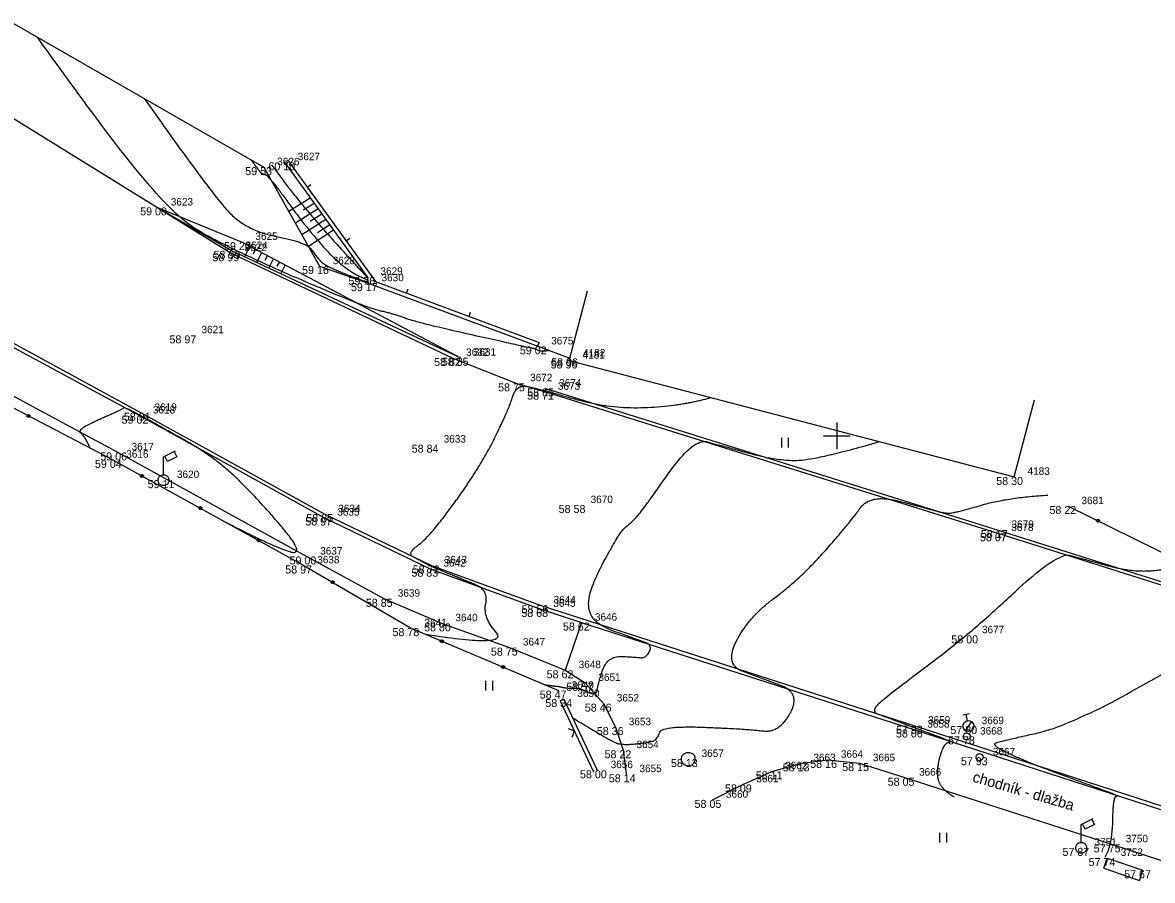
# Model space of a CAD drawing. Extents: x -704017 to -701500, y -1008977 to -1008450.
# Drawn here: x -701980.53 to -701938.17, y -1008866.67 to -1008834.5 of the extents above; entities that cross this region are included whole.
import ezdxf

# ---------------------------------------------------------------- set-up
doc = ezdxf.new("R2010")
doc.units = 0
for name, color, linetype in [('Z_body', 7, 'Continuous'), ('Z_body_cisla', 7, 'Continuous'), ('Z_body_vysky', 7, 'Continuous'), ('Z_budovy', 7, 'Continuous'), ('Z_chodnik', 7, 'Continuous'), ('Z_hekt_sit', 7, 'Continuous'), ('Z_komunikace', 7, 'Continuous'), ('Z_obruby', 7, 'Continuous'), ('Z_oploceni', 7, 'Continuous'), ('Z_popis', 7, 'Continuous'), ('Z_rozhrani_ploch', 7, 'Continuous'), ('Z_site_znaky_kanalizace', 7, 'Continuous'), ('Z_site_znaky_pilire', 7, 'Continuous'), ('Z_site_znaky_VO', 7, 'Continuous'), ('Z_site_znaky_vodovod', 7, 'Continuous'), ('Z_teren_hrany_paty', 7, 'Continuous'), ('Z_vrstevnice_hlavni', 7, 'Continuous'), ('Z_vrstevnice_vedlejsi', 7, 'Continuous'), ('Z_vstupy', 7, 'Continuous'), ('Z_zabradli', 7, 'Continuous')]:
    doc.layers.add(name, color=color, linetype=linetype)

# ---------------------------------------------------------------- blocks, each defined once
blk = doc.blocks.new('POINT_DISPLAY')
blk.add_line((0, 0), (0, 0))
blk = doc.blocks.new('Z210')
blk.add_line((0, 0), (0, 0.17))
blk = doc.blocks.new('Z530')
for p, q in [((-0.05, 0.03), (-0.03, 0.05)), ((-0.05, -0.03), (-0.05, 0.03)), ((-0.03, 0.05), (0.03, 0.05)), ((-0.03, -0.03), (-0.03, 0.03)), ((-0.03, 0.03), (0.03, 0.03)), ((-0.03, -0.03), (0.03, 0.03)), ((0.03, 0.05), (0.05, 0.03)), ((0.03, 0.03), (0.03, -0.03)), ((0.05, 0.03), (0.05, -0.03)), ((-0.03, -0.05), (-0.05, -0.03)), ((0.03, -0.03), (-0.03, -0.03)), ((0.03, -0.05), (-0.03, -0.05)), ((0.05, -0.03), (0.03, -0.05))]:
    blk.add_line(p, q)
blk = doc.blocks.new('Z212')
for p, q in [((-0.17, 0.17), (0, 0)), ((0, 0), (0.17, 0.17))]:
    blk.add_line(p, q)
blk = doc.blocks.new('Z306')
for p, q in [((-0.13, 0.17), (-0.13, -0.2)), ((0.13, 0.17), (0.13, -0.2))]:
    blk.add_line(p, q)
blk = doc.blocks.new('Z13')
for p, q in [((0, 0.88), (0.45, 1.1)), ((0, 0.2), (0, 0.88)), ((0.15, 0.7), (0.05, 0.9)), ((0.5, 0.88), (0.15, 0.7)), ((0.4, 1.07), (0.5, 0.88)), ((-0.2, 0.05), (-0.15, 0.15)), ((-0.2, -0.05), (-0.2, 0.05)), ((-0.15, 0.15), (-0.05, 0.2)), ((-0.05, 0.2), (0.05, 0.2)), ((0.05, 0.2), (0.15, 0.15)), ((0.15, 0.15), (0.2, 0.05)), ((0.2, 0.05), (0.2, -0.05)), ((-0.15, -0.15), (-0.2, -0.05)), ((-0.05, -0.2), (-0.15, -0.15)), ((0.05, -0.2), (-0.05, -0.2)), ((0.15, -0.15), (0.05, -0.2)), ((0.2, -0.05), (0.15, -0.15))]:
    blk.add_line(p, q)
blk = doc.blocks.new('Z620')
for p, q in [((-0.25, 0.05), (-0.23, 0.13)), ((-0.25, -0.05), (-0.25, 0.05)), ((-0.23, 0.13), (-0.17, 0.2)), ((-0.17, 0.2), (-0.05, 0.25)), ((-0.05, 0.25), (0.05, 0.25)), ((0.05, 0.25), (0.17, 0.2)), ((0.17, 0.2), (0.23, 0.13)), ((0.23, 0.13), (0.25, 0.05)), ((0.25, 0.05), (0.25, -0.05)), ((-0.2, -0.17), (-0.25, -0.05)), ((-0.13, -0.23), (-0.2, -0.17)), ((-0.05, -0.25), (-0.13, -0.23)), ((0.05, -0.25), (-0.05, -0.25)), ((0.13, -0.23), (0.05, -0.25)), ((0.2, -0.17), (0.13, -0.23)), ((0.25, -0.05), (0.2, -0.17))]:
    blk.add_line(p, q)
blk = doc.blocks.new('Z614')
for p, q in [((-0.13, 0.03), (-0.1, 0.08)), ((-0.13, -0.03), (-0.13, 0.03)), ((-0.1, 0.08), (-0.08, 0.1)), ((-0.08, 0.1), (-0.03, 0.13)), ((-0.03, 0.13), (0.03, 0.13)), ((0.03, 0.13), (0.08, 0.1)), ((0.08, 0.1), (0.1, 0.08)), ((0.1, 0.08), (0.13, 0.03)), ((0.13, 0.03), (0.13, -0.03)), ((-0.1, -0.08), (-0.13, -0.03)), ((-0.08, -0.1), (-0.1, -0.08)), ((-0.03, -0.13), (-0.08, -0.1)), ((0.03, -0.13), (-0.03, -0.13)), ((0.08, -0.1), (0.03, -0.13)), ((0.1, -0.08), (0.08, -0.1)), ((0.13, -0.03), (0.1, -0.08))]:
    blk.add_line(p, q)
blk = doc.blocks.new('Z18')
for p, q in [((-0.13, 0.45), (0.13, 0.45)), ((0, 0.2), (0, 0.45)), ((-0.2, 0.05), (-0.15, 0.15)), ((-0.2, -0.05), (-0.2, 0.05)), ((-0.15, 0.15), (-0.05, 0.2)), ((0.15, 0.15), (-0.15, -0.15)), ((-0.05, 0.2), (0.05, 0.2)), ((0.05, 0.2), (0.15, 0.15)), ((0.15, 0.15), (0.2, 0.05)), ((0.2, 0.05), (0.2, -0.05)), ((-0.15, -0.15), (-0.2, -0.05)), ((-0.05, -0.2), (-0.15, -0.15)), ((0.05, -0.2), (-0.05, -0.2)), ((0.15, -0.15), (0.05, -0.2)), ((0.2, -0.05), (0.15, -0.15))]:
    blk.add_line(p, q)

msp = doc.modelspace()

# ---------------------------------------------------------------- linework, layer by layer
at = {"layer": 'Z_budovy'}
for p, q in [((-701960.01, -1008847.09), (-701959.35, -1008844.56)), ((-701960.03, -1008847.17), (-701960.01, -1008847.09)), ((-701960.03, -1008847.17), (-701943.35, -1008851.54)), ((-701943.35, -1008851.54), (-701942.59, -1008848.65))]:
    msp.add_line(p, q, dxfattribs=at)
at = {"layer": 'Z_chodnik'}
for p, q in [((-701990.1, -1008843.54), (-701976.94, -1008850.62)), ((-701976.94, -1008850.62), (-701969.87, -1008854.52)), ((-701969.87, -1008854.52), (-701966.96, -1008856.11)), ((-701966.96, -1008856.11), (-701964.8, -1008857.03)), ((-701964.8, -1008857.03), (-701962.27, -1008857.94)), ((-701962.27, -1008857.94), (-701960.18, -1008858.79)), ((-701960.18, -1008858.79), (-701959.44, -1008859.26)), ((-701959.44, -1008859.26), (-701958.75, -1008860.04)), ((-701958.75, -1008860.04), (-701958.3, -1008860.92)), ((-701958.3, -1008860.92), (-701958.01, -1008861.79)), ((-701958.01, -1008861.79), (-701957.9, -1008862.69)), ((-701951.38, -1008862.28), (-701950.35, -1008862.15)), ((-701950.35, -1008862.15), (-701949.15, -1008862.27)), ((-701953.52, -1008863.07), (-701952.44, -1008862.58)), ((-701952.44, -1008862.58), (-701951.38, -1008862.28)), ((-701949.15, -1008862.27), (-701947.42, -1008862.82)), ((-701947.42, -1008862.82), (-701939.67, -1008865.32)), ((-701954.66, -1008863.65), (-701953.52, -1008863.07)), ((-701939.67, -1008865.32), (-701936.53, -1008866.35))]:
    msp.add_line(p, q, dxfattribs=at)
at = {"layer": 'Z_hekt_sit'}
for p, q in [((-701950, -1008849.5), (-701950, -1008850.5)), ((-701950.5, -1008850), (-701949.5, -1008850))]:
    msp.add_line(p, q, dxfattribs=at)
at = {"layer": 'Z_komunikace'}
for p, q in [((-701985.96, -1008834.96), (-701975.47, -1008841.43)), ((-701975.47, -1008841.43), (-701972.71, -1008843.15)), ((-701989.62, -1008841.76), (-701976.08, -1008849.13)), ((-701972.71, -1008843.15), (-701964.4, -1008847.08)), ((-701964.4, -1008847.08), (-701962, -1008848.03)), ((-701962, -1008848.03), (-701960.96, -1008848.34)), ((-701960.96, -1008848.34), (-701943.96, -1008853.65)), ((-701976.08, -1008849.13), (-701969.19, -1008852.93)), ((-701969.19, -1008852.93), (-701965.2, -1008854.86)), ((-701943.96, -1008853.65), (-701935.05, -1008856.48)), ((-701965.2, -1008854.86), (-701961.12, -1008856.35)), ((-701961.12, -1008856.35), (-701947.08, -1008860.87)), ((-701947.08, -1008860.87), (-701937.33, -1008864.04))]:
    msp.add_line(p, q, dxfattribs=at)
at = {"layer": 'Z_obruby'}
for p, q in [((-701989.65, -1008841.93), (-701976.14, -1008849.24)), ((-701960.91, -1008848.22), (-701960.96, -1008848.34)), ((-701960.91, -1008848.22), (-701943.95, -1008853.53)), ((-701976.14, -1008849.24), (-701969.23, -1008853.06)), ((-701969.23, -1008853.06), (-701965.25, -1008854.98)), ((-701943.95, -1008853.53), (-701935.02, -1008856.35)), ((-701965.25, -1008854.98), (-701961.13, -1008856.49)), ((-701961.13, -1008856.49), (-701959.57, -1008857)), ((-701959.57, -1008857), (-701947.11, -1008861.01)), ((-701947.11, -1008861.01), (-701937.41, -1008864.16))]:
    msp.add_line(p, q, dxfattribs=at)
at = {"layer": 'Z_oploceni'}
for p, q in [((-701970.71, -1008839.74), (-701967.61, -1008844.04)), ((-701970.59, -1008839.65), (-701967.3, -1008844.21)), ((-701967.61, -1008844.04), (-701967.57, -1008844.27)), ((-701967.57, -1008844.27), (-701961.21, -1008846.64)), ((-701967.3, -1008844.21), (-701961.16, -1008846.5)), ((-701961.21, -1008846.64), (-701961.16, -1008846.5)), ((-701960.37, -1008859.93), (-701960.23, -1008859.87)), ((-701960.37, -1008859.93), (-701959.12, -1008862.6)), ((-701960.23, -1008859.87), (-701958.98, -1008862.54))]:
    msp.add_line(p, q, dxfattribs=at)
at = {"layer": 'Z_rozhrani_ploch'}
msp.add_line((-701959.57, -1008857), (-701960.18, -1008858.79), dxfattribs=at)
at = {"layer": 'Z_site_znaky_pilire'}
for p, q in [((-701939.99, -1008866.21), (-701939.86, -1008865.83)), ((-701939.86, -1008865.83), (-701938.53, -1008866.29)), ((-701939.99, -1008866.21), (-701938.66, -1008866.67)), ((-701938.66, -1008866.67), (-701938.53, -1008866.29))]:
    msp.add_line(p, q, dxfattribs=at)
at = {"layer": 'Z_teren_hrany_paty'}
for p, q in [((-701980.93, -1008834.5), (-701971.48, -1008839.92)), ((-701971.48, -1008839.92), (-701969.4, -1008843.63)), ((-701975.47, -1008841.43), (-701972.3, -1008842.73)), ((-701975.47, -1008841.43), (-701972.67, -1008843.06)), ((-701969.75, -1008841.08), (-701970.55, -1008841.59)), ((-701969.6, -1008841.28), (-701970.01, -1008841.54)), ((-701969.45, -1008841.48), (-701970.3, -1008842.02)), ((-701969.16, -1008841.89), (-701970.06, -1008842.46)), ((-701969.31, -1008841.69), (-701969.74, -1008841.96)), ((-701968.87, -1008842.29), (-701969.81, -1008842.9)), ((-701969.01, -1008842.09), (-701969.47, -1008842.38)), ((-701972.3, -1008842.73), (-701964.11, -1008847.07)), ((-701972.67, -1008843.06), (-701964.11, -1008847.07)), ((-701972.01, -1008842.88), (-701972.21, -1008843.28)), ((-701971.79, -1008843), (-701971.88, -1008843.19)), ((-701971.57, -1008843.12), (-701971.75, -1008843.49)), ((-701971.35, -1008843.24), (-701971.44, -1008843.42)), ((-701971.12, -1008843.35), (-701971.3, -1008843.7)), ((-701970.9, -1008843.47), (-701970.99, -1008843.64)), ((-701970.68, -1008843.59), (-701970.85, -1008843.91)), ((-701969.4, -1008843.63), (-701967.57, -1008844.27))]:
    msp.add_line(p, q, dxfattribs=at)
at = {"layer": 'Z_vrstevnice_hlavni'}
for points in [[(-701960.81, -1008846.79), (-701960.817, -1008846.817), (-701961.175, -1008846.826), (-701961.269, -1008846.743), (-701961.551, -1008846.691), (-701965.732, -1008845.758), (-701966.67, -1008845.405), (-701967.62, -1008845.21), (-701972.652, -1008843.044), (-701975.47, -1008841.43), (-701979.969, -1008835.051)], [(-701973.049, -1008853.163), (-701971.107, -1008854.174), (-701969.87, -1008854.52), (-701971.8, -1008852.247), (-701973.376, -1008850.768), (-701975.322, -1008849.674), (-701976.129, -1008849.22), (-701976.74, -1008848.915), (-701976.747, -1008848.992), (-701978.519, -1008849.77), (-701978.21, -1008849.992), (-701978.001, -1008850.45)], [(-701945.592, -1008863.551), (-701946.128, -1008863.237), (-701946.266, -1008862.499), (-701945.975, -1008861.49), (-701945.618, -1008861.495), (-701947.096, -1008860.945), (-701948.347, -1008860.477), (-701948.64, -1008860.368), (-701948.442, -1008859.978), (-701945.06, -1008857.48), (-701941.732, -1008854.358), (-701940.831, -1008854.595), (-701938.89, -1008855.128), (-701937.364, -1008854.968), (-701936.816, -1008854.858), (-701935.4, -1008855.26)]]:
    msp.add_open_spline(points, degree=2, dxfattribs=at)
at = {"layer": 'Z_vrstevnice_vedlejsi'}
for points in [[(-701975.965, -1008837.348), (-701973.588, -1008840.718), (-701972.176, -1008842.304), (-701969.906, -1008842.728), (-701969.525, -1008843.258), (-701969.131, -1008843.692), (-701967.575, -1008844.239)], [(-701971.961, -1008839.644), (-701971.706, -1008840.005), (-701971.555, -1008840.175), (-701971.311, -1008840.221), (-701969.874, -1008842.223), (-701968.386, -1008843.862), (-701967.592, -1008844.141)], [(-701971.183, -1008839.851), (-701970.222, -1008841.188), (-701967.64, -1008844.033), (-701967.609, -1008844.044)], [(-701965.426, -1008857.436), (-701962.27, -1008857.94), (-701963.271, -1008856.805), (-701963.053, -1008855.785), (-701964.026, -1008855.386), (-701965.214, -1008854.893), (-701965.684, -1008854.644), (-701966.121, -1008854.415), (-701965.21, -1008853.728), (-701963.333, -1008851.112), (-701962.277, -1008848.952), (-701962, -1008848.03), (-701960.946, -1008848.306), (-701958.416, -1008849.001), (-701955.756, -1008848.861), (-701954.723, -1008848.56)], [(-701960.974, -1008859.324), (-701960.636, -1008859.378), (-701960.388, -1008859.398), (-701960.14, -1008859.463), (-701959.68, -1008859.446), (-701959.001, -1008859.756), (-701958.955, -1008859.28), (-701958.59, -1008858.254), (-701957.564, -1008858.293), (-701957.165, -1008858.343), (-701956.9, -1008857.859), (-701957.398, -1008857.673), (-701959.783, -1008856.78), (-701958.173, -1008853.609), (-701957.707, -1008853.264), (-701957.256, -1008852.756), (-701955.382, -1008850.082), (-701954.345, -1008850.358), (-701952.181, -1008850.953), (-701950.667, -1008850.873), (-701948.405, -1008850.216)], [(-701959.899, -1008860.577), (-701958.508, -1008861.415), (-701958.072, -1008861.604), (-701956.994, -1008861.494), (-701956.726, -1008861.364), (-701956.55, -1008860.866), (-701953.386, -1008860.987), (-701952.154, -1008861.142), (-701951.337, -1008859.649), (-701952.872, -1008859.075), (-701954.211, -1008858.574), (-701953.308, -1008856.794), (-701951.383, -1008855.372), (-701949.526, -1008853.276), (-701948.741, -1008852.157), (-701946.47, -1008852.761), (-701945.945, -1008852.905), (-701945.578, -1008852.886), (-701943.581, -1008852.305), (-701942.087, -1008852.221)], [(-701939.935, -1008865.801), (-701939.67, -1008865.32), (-701939.638, -1008863.511), (-701939.4, -1008863.514), (-701940.385, -1008863.148), (-701942.901, -1008862.229), (-701944.263, -1008861.578), (-701943.736, -1008861.425), (-701941.116, -1008860.827), (-701935.376, -1008857.56), (-701935.307, -1008857.501), (-701934.732, -1008857.583), (-701934.543, -1008856.86), (-701933.935, -1008856.831), (-701933.657, -1008856.862), (-701933.229, -1008856.893), (-701931.39, -1008856.712), (-701930.335, -1008856.196), (-701930.001, -1008857.013), (-701929.207, -1008856.306), (-701928.557, -1008855.982), (-701926.449, -1008854.933)]]:
    msp.add_open_spline(points, degree=2, dxfattribs=at)
at = {"layer": 'Z_vstupy'}
msp.add_line((-701961.21, -1008846.64), (-701960.01, -1008847.09), dxfattribs=at)
at = {"layer": 'Z_zabradli'}
for p, q in [((-701990.27, -1008844.03), (-701977.14, -1008850.9)), ((-701977.14, -1008850.9), (-701969.98, -1008854.86)), ((-701941.33, -1008852.63), (-701934.97, -1008855.77)), ((-701969.98, -1008854.86), (-701965.96, -1008857.21)), ((-701965.96, -1008857.21), (-701960.44, -1008859.55))]:
    msp.add_line(p, q, dxfattribs=at)

# ---------------------------------------------------------------- block references
at = {"layer": 'Z_body'}
for p in [(-701970.71, -1008839.74), (-701971.48, -1008839.92), (-701975.47, -1008841.43), (-701972.3, -1008842.73), (-701972.71, -1008843.15), (-701972.67, -1008843.06), (-701969.4, -1008843.63), (-701967.61, -1008844.04), (-701967.57, -1008844.27), (-701974.32, -1008846.23), (-701961.21, -1008846.64), (-701964.4, -1008847.08), (-701964.11, -1008847.07), (-701960.03, -1008847.17), (-701960.01, -1008847.09), (-701962, -1008848.03), (-701960.91, -1008848.22), (-701960.96, -1008848.34), (-701976.14, -1008849.24), (-701976.08, -1008849.13), (-701965.24, -1008850.33), (-701976.94, -1008850.62), (-701977.14, -1008850.9), (-701943.35, -1008851.54), (-701975.24, -1008851.66), (-701959.73, -1008852.59), (-701941.33, -1008852.63), (-701969.23, -1008853.06), (-701969.19, -1008852.93), (-701943.96, -1008853.65), (-701943.95, -1008853.53), (-701969.87, -1008854.52), (-701969.98, -1008854.86), (-701965.25, -1008854.98), (-701965.2, -1008854.86), (-701966.96, -1008856.11), (-701961.13, -1008856.49), (-701961.12, -1008856.35), (-701964.8, -1008857.03), (-701959.57, -1008857), (-701965.96, -1008857.21), (-701945.06, -1008857.48), (-701962.27, -1008857.94), (-701960.18, -1008858.79), (-701960.44, -1008859.55), (-701959.44, -1008859.26), (-701960.23, -1008859.87), (-701958.75, -1008860.04), (-701958.3, -1008860.92), (-701947.08, -1008860.87), (-701945.07, -1008860.88), (-701947.11, -1008861.01), (-701945.13, -1008861.27), (-701958.01, -1008861.79), (-701955.57, -1008862.12), (-701950.35, -1008862.15), (-701944.65, -1008862.05), (-701958.98, -1008862.54), (-701952.44, -1008862.58), (-701951.38, -1008862.28), (-701949.15, -1008862.27), (-701957.9, -1008862.69), (-701947.42, -1008862.82), (-701953.52, -1008863.07), (-701954.66, -1008863.65), (-701940.84, -1008865.45), (-701939.67, -1008865.32), (-701939.86, -1008865.83), (-701938.53, -1008866.29)]:
    msp.add_blockref('POINT_DISPLAY', p, dxfattribs=at)
at = {"layer": 'Z_oploceni'}
for name, p, rotation in [('Z210', (-701969.86, -1008840.67), -54.20000000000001), ('Z210', (-701968.4, -1008842.69), -54.20000000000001), ('Z210', (-701966.13, -1008844.65), -20.399999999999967), ('Z210', (-701963.79, -1008845.52), -20.399999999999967), ('Z212', (-701959.84, -1008861.07), 115.1)]:
    msp.add_blockref(name, p, dxfattribs=dict(at, rotation=rotation))
at = {"layer": 'Z_popis'}
for p in [(-701951.95, -1008850.24), (-701963.04, -1008859.35), (-701946.02, -1008865.05)]:
    msp.add_blockref('Z306', p, dxfattribs=at)
at = {"layer": 'Z_site_znaky_kanalizace'}
msp.add_blockref('Z620', (-701955.57, -1008862.12), dxfattribs=at)
at = {"layer": 'Z_site_znaky_VO'}
for p in [(-701975.24, -1008851.66), (-701940.84, -1008865.45)]:
    msp.add_blockref('Z13', p, dxfattribs=at)
at = {"layer": 'Z_site_znaky_vodovod', "rotation": 10.799999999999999}
for name, p in [('Z18', (-701945.07, -1008860.88)), ('Z614', (-701945.13, -1008861.27)), ('Z614', (-701944.65, -1008862.05))]:
    msp.add_blockref(name, p, dxfattribs=at)
at = {"layer": 'Z_zabradli'}
for p, rotation in [((-701980.3, -1008849.25), 152.4), ((-701976.05, -1008851.5), 151.1), ((-701973.86, -1008852.71), 151.1), ((-701940.21, -1008853.18), -26.300000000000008), ((-701971.67, -1008853.92), 151.1), ((-701968.9, -1008855.49), 149.7), ((-701964.81, -1008857.7), 157), ((-701962.51, -1008858.67), 157)]:
    msp.add_blockref('Z530', p, dxfattribs=dict(at, rotation=rotation))

# ---------------------------------------------------------------- texts
at = {"layer": 'Z_body_cisla'}
for s, p in [('3626', (-701970.98, -1008839.85)), ('3627', (-701970.21, -1008839.66)), ('3623', (-701974.97, -1008841.36)), ('3624', (-701972.17, -1008842.99)), ('3625', (-701971.8, -1008842.65)), ('3622', (-701972.21, -1008843.07)), ('3628', (-701968.9, -1008843.56)), ('3629', (-701967.11, -1008843.96)), ('3630', (-701967.07, -1008844.2)), ('3621', (-701973.82, -1008846.15)), ('3675', (-701960.71, -1008846.57)), ('3632', (-701963.9, -1008847)), ('3631', (-701963.61, -1008846.99)), ('4181', (-701959.53, -1008847.1)), ('4182', (-701959.51, -1008847.02)), ('3672', (-701961.5, -1008847.95)), ('3673', (-701960.46, -1008848.27)), ('3674', (-701960.41, -1008848.15)), ('3618', (-701975.64, -1008849.16)), ('3619', (-701975.58, -1008849.06)), ('3617', (-701976.44, -1008850.54)), ('3633', (-701964.74, -1008850.25)), ('3616', (-701976.64, -1008850.82)), ('4183', (-701942.85, -1008851.46)), ('3620', (-701974.74, -1008851.58)), ('3670', (-701959.23, -1008852.52)), ('3681', (-701940.83, -1008852.56)), ('3635', (-701968.73, -1008852.99)), ('3634', (-701968.69, -1008852.86)), ('3678', (-701943.46, -1008853.57)), ('3679', (-701943.45, -1008853.45)), ('3637', (-701969.37, -1008854.45)), ('3638', (-701969.48, -1008854.78)), ('3643', (-701964.7, -1008854.78)), ('3642', (-701964.75, -1008854.9)), ('3639', (-701966.46, -1008856.03)), ('3645', (-701960.63, -1008856.41)), ('3644', (-701960.62, -1008856.28)), ('3640', (-701964.3, -1008856.95)), ('3646', (-701959.07, -1008856.93)), ('3641', (-701965.46, -1008857.14)), ('3677', (-701944.56, -1008857.4)), ('3647', (-701961.77, -1008857.86)), ('3648', (-701959.68, -1008858.71)), ('3649', (-701959.94, -1008859.48)), ('3651', (-701958.94, -1008859.19)), ('3650', (-701959.73, -1008859.79)), ('3652', (-701958.25, -1008859.96)), ('3659', (-701946.58, -1008860.79)), ('3669', (-701944.57, -1008860.81)), ('3653', (-701957.8, -1008860.85)), ('3658', (-701946.61, -1008860.94)), ('3668', (-701944.63, -1008861.2)), ('3654', (-701957.51, -1008861.71)), ('3657', (-701955.07, -1008862.04)), ('3664', (-701949.85, -1008862.07)), ('3667', (-701944.15, -1008861.98)), ('3656', (-701958.48, -1008862.46)), ('3662', (-701951.94, -1008862.5)), ('3663', (-701950.88, -1008862.2)), ('3665', (-701948.65, -1008862.2)), ('3655', (-701957.4, -1008862.61)), ('3666', (-701946.92, -1008862.74)), ('3661', (-701953.02, -1008862.99)), ('3660', (-701954.16, -1008863.57)), ('3751', (-701940.34, -1008865.37)), ('3750', (-701939.17, -1008865.24)), ('3752', (-701939.36, -1008865.75))]:
    msp.add_text(s, height=0.28, dxfattribs=at).set_placement(p)
at = {"layer": 'Z_body_vysky'}
for s, p in [('60 10', (-701971.31, -1008840.04)), ('59 53', (-701972.18, -1008840.22)), ('59 00', (-701976.12, -1008841.73)), ('59 20', (-701972.975, -1008843.03)), ('58 99', (-701973.41, -1008843.45)), ('58 99', (-701973.37, -1008843.36)), ('59 16', (-701970.05, -1008843.93)), ('59 76', (-701968.31, -1008844.34)), ('59 17', (-701968.22, -1008844.57)), ('58 97', (-701975.02, -1008846.53)), ('59 02', (-701961.885, -1008846.94)), ('58 82', (-701965.1, -1008847.38)), ('58 85', (-701964.81, -1008847.37)), ('58 96', (-701960.73, -1008847.47)), ('58 96', (-701960.71, -1008847.39)), ('58 75', (-701962.7, -1008848.33)), ('58 85', (-701961.61, -1008848.52)), ('58 71', (-701961.61, -1008848.64)), ('59 02', (-701976.815, -1008849.54)), ('58 91', (-701976.73, -1008849.43)), ('58 84', (-701965.94, -1008850.63)), ('59 06', (-701977.615, -1008850.92)), ('59 04', (-701977.815, -1008851.2)), ('58 30', (-701944.025, -1008851.84)), ('59 11', (-701975.84, -1008851.96)), ('58 58', (-701960.43, -1008852.89)), ('58 22', (-701942.03, -1008852.93)), ('58 97', (-701969.93, -1008853.36)), ('58 85', (-701969.89, -1008853.23)), ('58 07', (-701944.635, -1008853.95)), ('58 17', (-701944.6, -1008853.83)), ('59 00', (-701970.52, -1008854.82)), ('58 97', (-701970.68, -1008855.16)), ('58 83', (-701965.95, -1008855.28)), ('58 72', (-701965.9, -1008855.16)), ('58 85', (-701967.66, -1008856.41)), ('58 68', (-701961.83, -1008856.79)), ('58 56', (-701961.82, -1008856.65)), ('58 80', (-701965.475, -1008857.33)), ('58 62', (-701960.27, -1008857.3)), ('58 78', (-701966.66, -1008857.51)), ('58 00', (-701945.71, -1008857.78)), ('58 75', (-701962.97, -1008858.24)), ('58 62', (-701960.88, -1008859.09)), ('58 57', (-701960.14, -1008859.56)), ('58 47', (-701961.14, -1008859.85)), ('58 34', (-701960.93, -1008860.17)), ('58 46', (-701959.45, -1008860.34)), ('58 36', (-701959, -1008861.22)), ('57 93', (-701947.78, -1008861.17)), ('57 80', (-701945.745, -1008861.18)), ('58 06', (-701947.785, -1008861.31)), ('57 78', (-701945.83, -1008861.57)), ('58 22', (-701958.71, -1008862.09)), ('58 13', (-701956.22, -1008862.42)), ('58 16', (-701951, -1008862.45)), ('57 93', (-701945.35, -1008862.35)), ('58 00', (-701959.63, -1008862.84)), ('58 11', (-701953.04, -1008862.88)), ('58 13', (-701952.03, -1008862.58)), ('58 15', (-701949.8, -1008862.57)), ('58 14', (-701958.55, -1008862.99)), ('58 09', (-701954.195, -1008863.37)), ('58 05', (-701948.095, -1008863.12)), ('58 05', (-701955.335, -1008863.95)), ('57 87', (-701941.54, -1008865.75)), ('57 75', (-701940.37, -1008865.62)), ('57 74', (-701940.56, -1008866.13)), ('57 67', (-701939.23, -1008866.59))]:
    msp.add_text(s, height=0.3, dxfattribs=at).set_placement(p)
at = {"layer": 'Z_popis'}
msp.add_text('chodník - dlažba', height=0.4, rotation=343.8, dxfattribs=at).set_placement((-701944.94, -1008862.96))

doc.saveas('drawing.dxf')
